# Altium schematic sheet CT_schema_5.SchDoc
size 301 x 258 mm
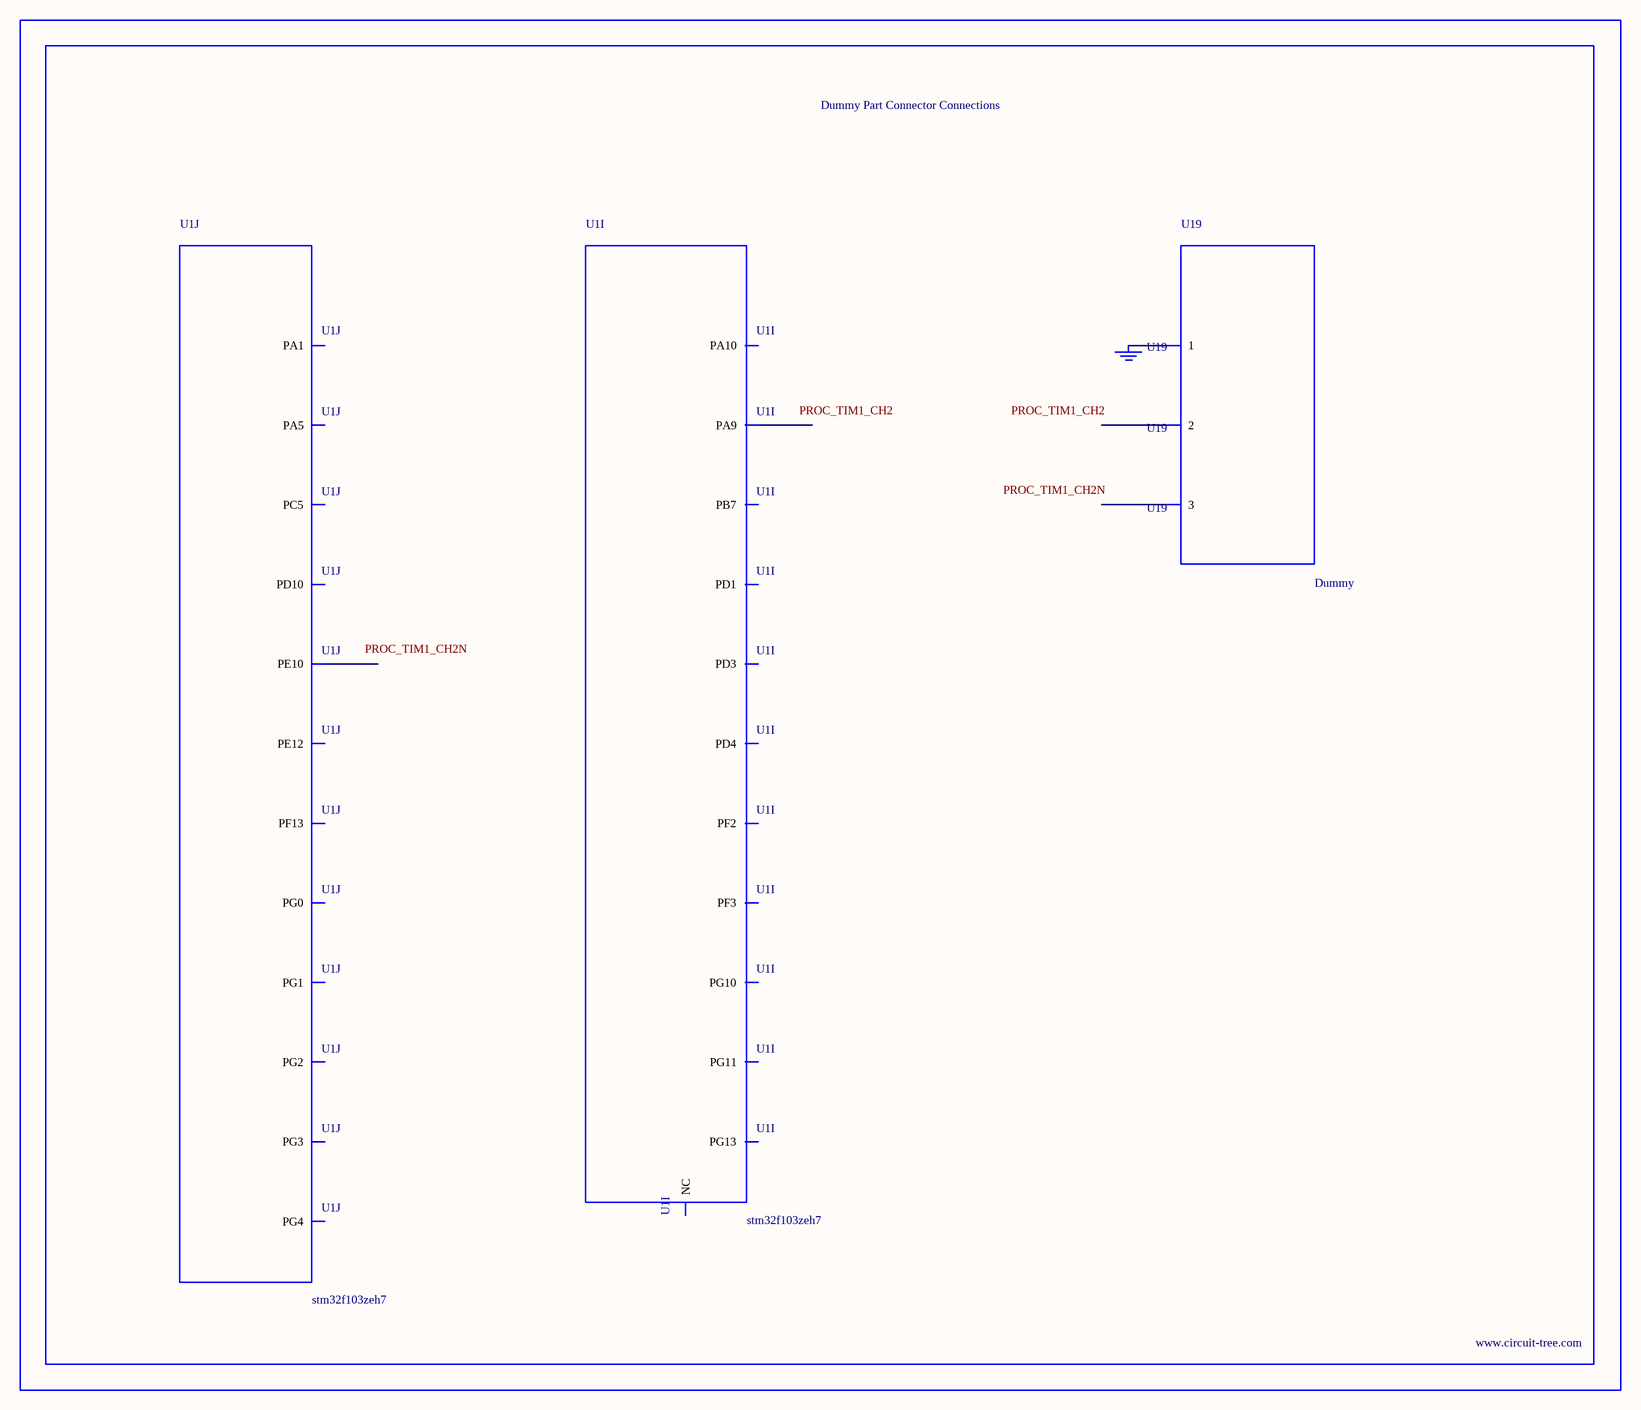
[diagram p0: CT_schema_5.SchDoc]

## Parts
BORDER4  (no value)
GND_INSTANCE_4_0  (no value)
U1  stm32f103zeh7  [LFBGA144]  (parts I,J of 10)
U19  Dummy  [DUMMY_PACKAGE_198]

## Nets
NetGND_INSTANCE_4_0_0: GND_INSTANCE_4_0.0(GND) U19.1

Not connected (* = marked no-connect by the designer): U1 C8(PG11) C9(PD4) C11(NC) D4(PF2) D6(PB7) D7(PG13) D8(PG10) D9(PD3) D10(PD1) D11(PA10) D12(PA9) E2(PF3) J6(PG1) J7(PE10) J8(PE12) J9(PD10) J10(PG4) J11(PG3) J12(PG2) K2(PA1) K3(PA5) K4(PC5) K5(PF13) K6(PG0); U19 2 3

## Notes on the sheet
- Labels drawn without touching a wire or pin: PROC_TIM1_CH2, PROC_TIM1_CH2N

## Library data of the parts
BORDER4 = BORDER_PAGE4
GND_INSTANCE_4_0 = GND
